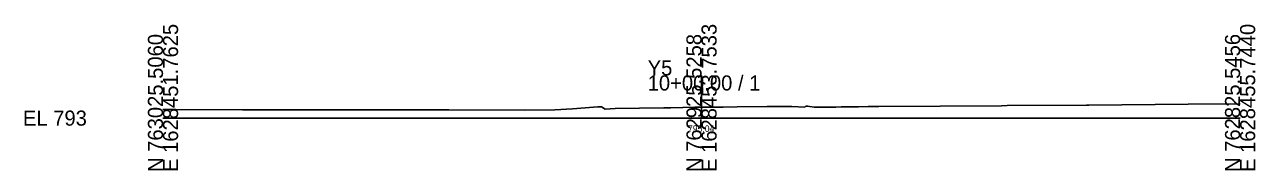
# Model space of a CAD drawing. Extents: x -26 to 203, y -10 to 6017.
# Drawn here: x -25.7 to 202.8, y -9.7 to 17.3 of the extents above; entities that cross this region are included whole.
import ezdxf

# ---------------------------------------------------------------- set-up
doc = ezdxf.new("R2010")
doc.units = 0
for name, color, linetype in [('Default', 7, 'Continuous'), ('Exist Cross Section Cell', 7, 'Continuous'), ('Exist XS Center Line Elevation Label', 7, 'Continuous'), ('Exist XS Ground Line', 7, 'Continuous')]:
    doc.layers.add(name, color=color, linetype=linetype)

msp = doc.modelspace()

# ---------------------------------------------------------------- linework, layer by layer
at = {"layer": 'Exist Cross Section Cell'}
for p, q in [((100, 0), (100, 7.92)), ((0, 0), (100, 0)), ((100, 0), (200, 0))]:
    msp.add_line(p, q, dxfattribs=at)
at = {"layer": 'Exist XS Ground Line'}
msp.add_lwpolyline([(0, 1.6), (2.41, 1.59), (14.74, 1.54), (17.87, 1.54), (21.51, 1.54), (33.85, 1.54), (51.52, 1.54), (53.06, 1.55), (67.04, 1.5), (72.75, 1.55), (76.04, 1.69), (80.75, 2.07), (81.42, 2.11), (82.13, 1.65), (83.99, 1.78), (92.97, 1.88), (94.29, 1.91), (98.78, 2.03), (100, 2.04), (103.99, 2.06), (106.62, 2.09), (112.19, 2.14), (116.41, 2.17), (116.74, 2.14), (119.15, 2.04), (119.38, 2.24), (119.7, 2.24), (120.02, 2.18), (120.97, 2), (122.88, 2.03), (124.96, 2.05), (125.91, 2.07), (127.84, 2.11), (129.13, 2.12), (130.96, 2.15), (132.89, 2.14), (155.72, 2.3), (156.78, 2.33), (171.49, 2.41), (171.93, 2.42), (190.34, 2.56), (200, 2.64)], dxfattribs=at)

# ---------------------------------------------------------------- texts
at = {"layer": 'Default'}
msp.add_text('-', height=0.0001, dxfattribs=at).set_placement((0, 0))
at = {"layer": 'Exist Cross Section Cell'}
for s, p in [('E 1628451.7625', (2.8, -10)), ('E 1628453.7533', (102.8, -10)), ('E 1628455.7440', (202.8, -10)), ('N 763025.5060', (0, -10)), ('N 762925.5258', (100, -10)), ('N 762825.5456', (200, -10))]:
    msp.add_text(s, height=2.8, rotation=90, dxfattribs=at).set_placement(p)
for s, p in [('Y5', (90, 7.92)), ('10+00.00 / 1', (90, 5.12)), ('EL 793', (-26, -1.4))]:
    msp.add_text(s, height=2.8, dxfattribs=at).set_placement(p)
at = {"layer": 'Exist XS Center Line Elevation Label'}
msp.add_text('795.04', height=1.2, dxfattribs=at).set_placement((97.48, -2.56))

doc.saveas('drawing.dxf')
